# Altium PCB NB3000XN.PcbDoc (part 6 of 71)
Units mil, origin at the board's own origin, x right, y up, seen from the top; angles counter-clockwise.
Board outline 9527.56 x 6929.77 mil, 6 copper layers (Top Layer, GND+SHIELD, MidLayer1, MidLayer2, P2 - 3V3+5V0, Bottom Layer), stack 62.375 mil thick; 832 components, 1027 nets, 4655 pads, 4981 vias.
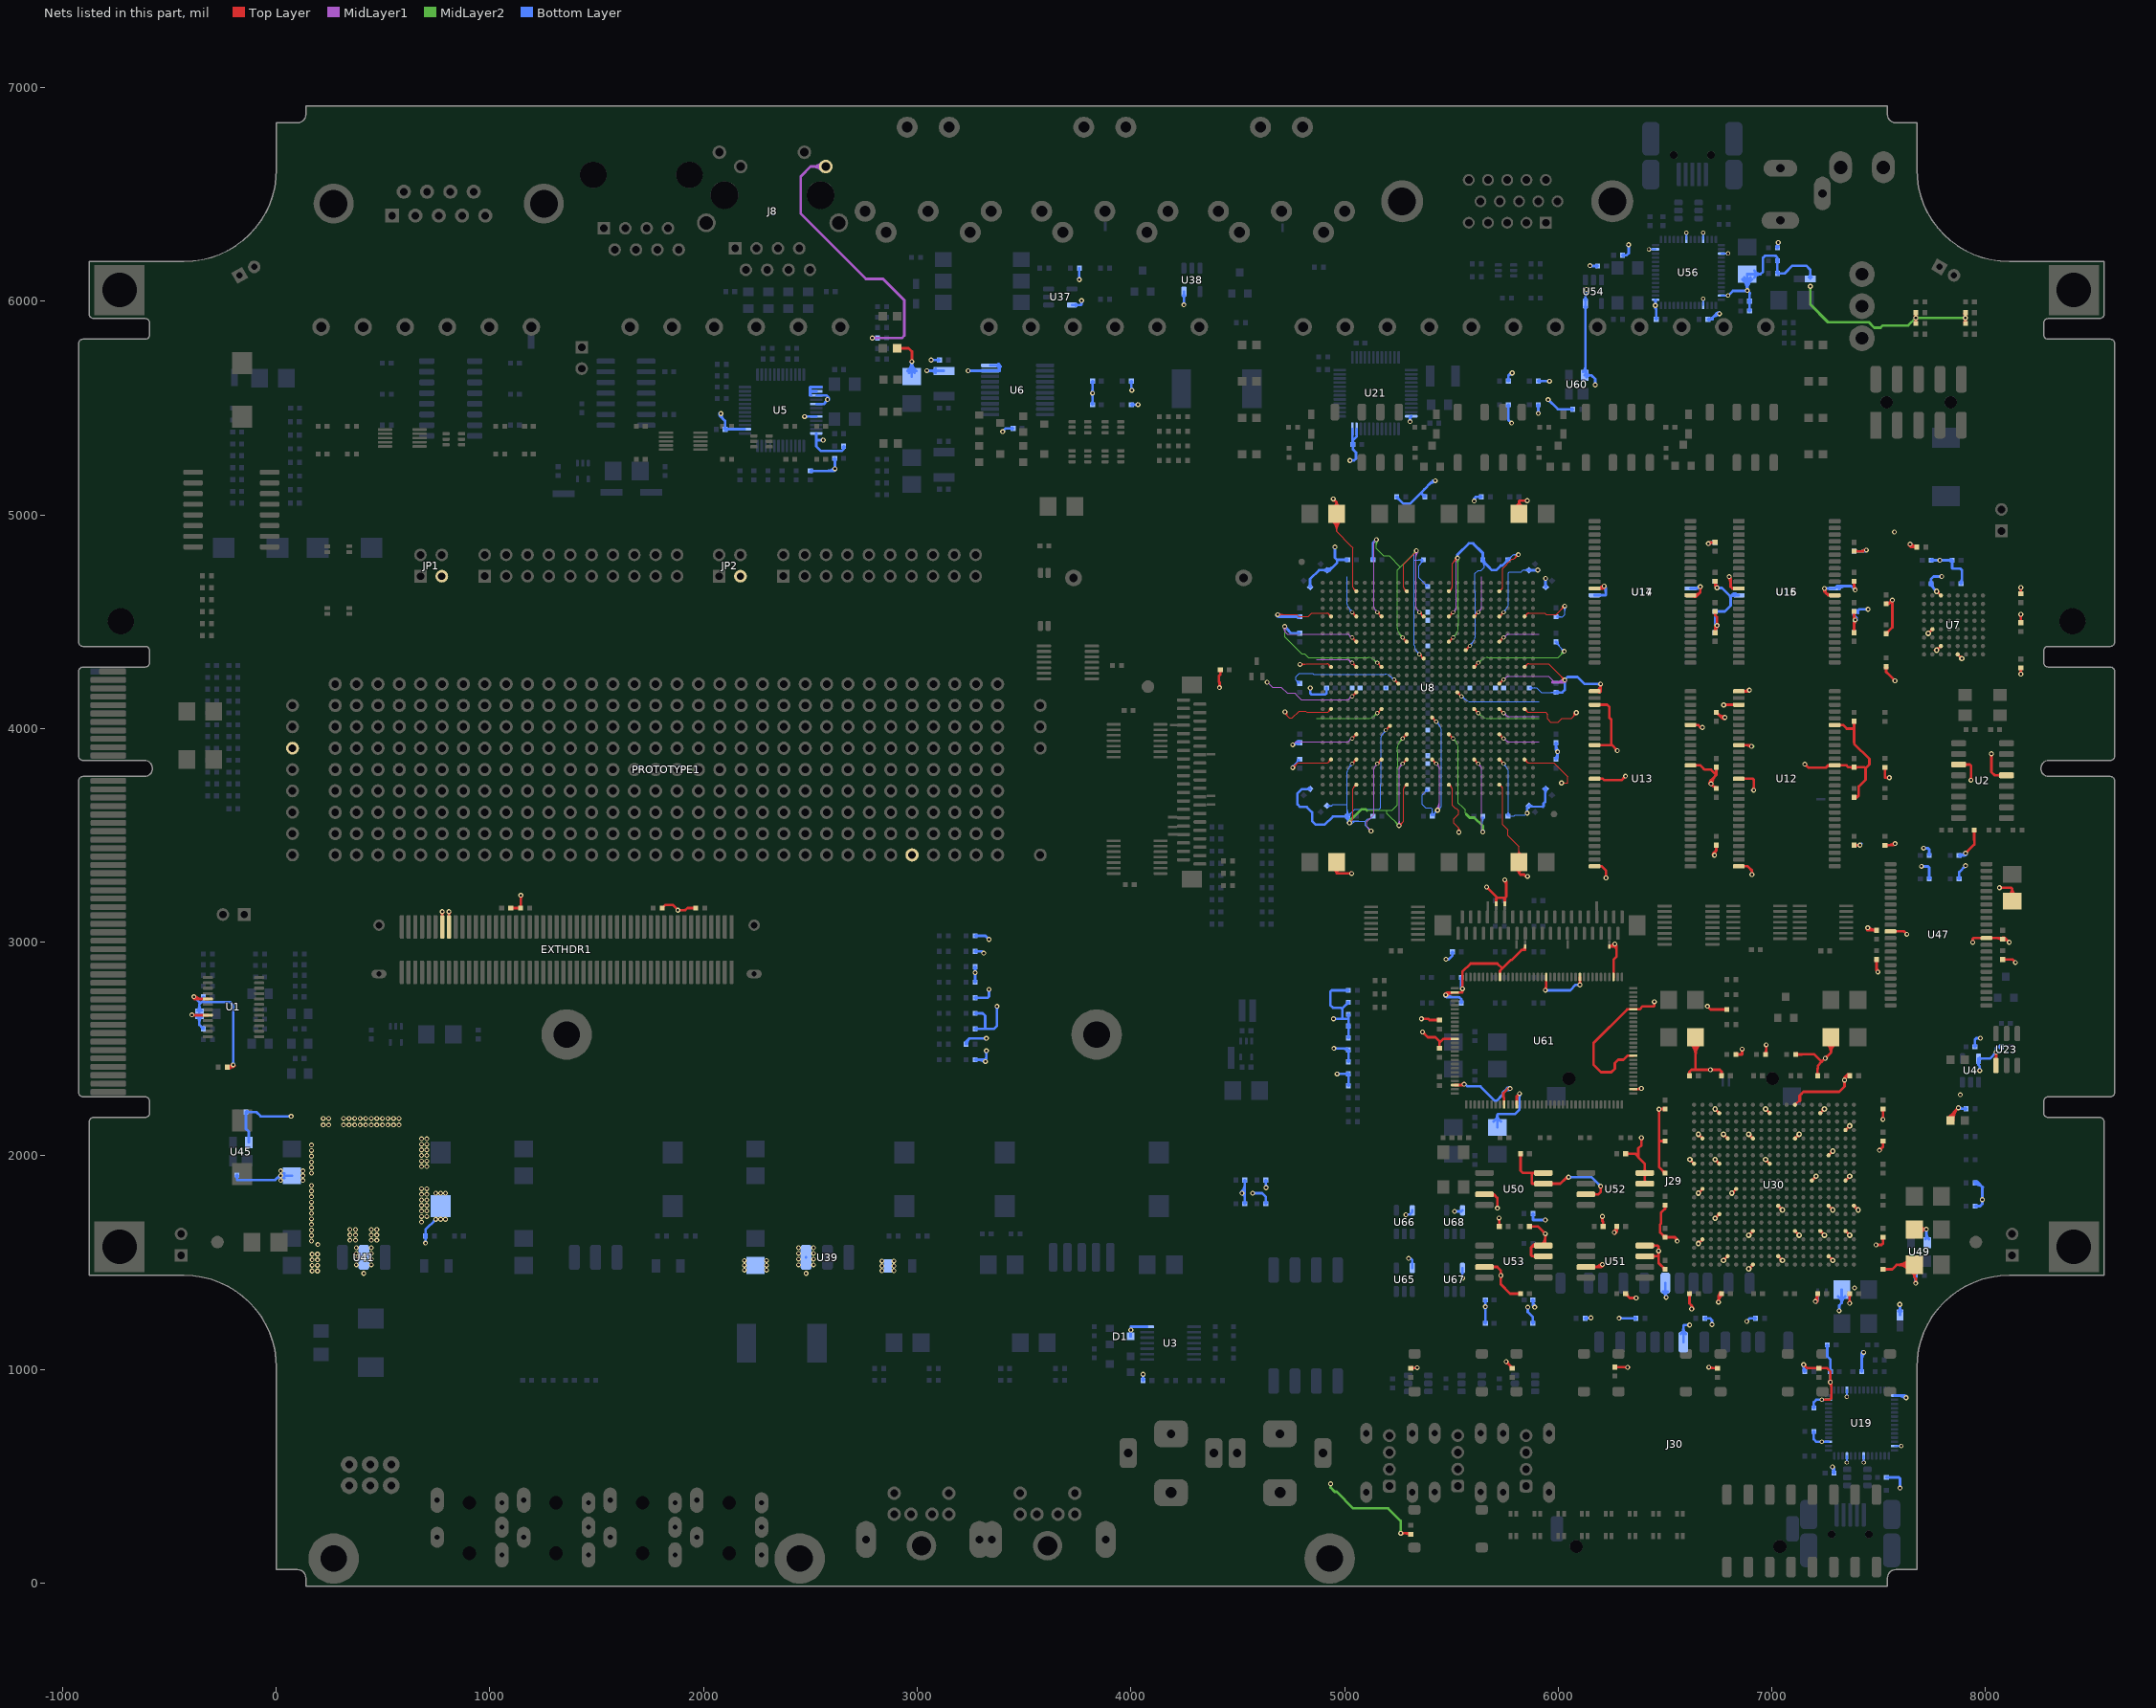
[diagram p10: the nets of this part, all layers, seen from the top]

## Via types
v1: diameter 23, hole 11.81, Top Layer to Bottom Layer, 3672 vias
v2: diameter 26, hole 11.81, Top Layer to Bottom Layer, 461 vias
v3: diameter 19, hole 11.81, Top Layer to Bottom Layer, tented both sides, 396 vias
v4: diameter 23.62, hole 11.81, Top Layer to Bottom Layer, 288 vias
v5: diameter 20, hole 11.81, Top Layer to Bottom Layer, 91 vias
v6: diameter 23, hole 11.81, Top Layer to Bottom Layer, tented both sides, 50 vias
v7: diameter 31, hole 11.81, Top Layer to Bottom Layer, 15 vias
v8: diameter 27.56, hole 11.81, Top Layer to Bottom Layer, tented both sides, 4 vias
v9: diameter 29, hole 11.81, Top Layer to Bottom Layer, 3 vias
v10: diameter 21, hole 11.81, Top Layer to Bottom Layer, 1 vias

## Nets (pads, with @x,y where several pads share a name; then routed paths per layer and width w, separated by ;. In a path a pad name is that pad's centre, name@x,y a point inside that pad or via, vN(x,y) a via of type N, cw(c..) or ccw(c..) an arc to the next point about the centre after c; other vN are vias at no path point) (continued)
3V3: C20.1 C21.1 C35.1 C36.1 C37.2 C39.2 C49.1 C50.2 C51.2 C52.2 C54.2 C55.1 C56.1 C57.1 C58.1 C59.1 C60.1 C63.1 C64.1 C65.1 C66.1 C67.1 C68.1 C69.1 C70.1 C71.1 C72.1 C73.1 C74.1 C75.1 C76.1 C77.1 C78.1 C79.1 C80.1 C81.1 C82.1 C83.1 C84.1 C85.1 C86.1 C90.2 C91.2 C92.2 C93.1 C94.1 C95.1 C96.1 C126.1 C127.1 C136.1 C137.1 C153.1 C154.1 C155.1 C156.1 C158.1 C159.2 C160.1 C161.2 C162.1 C163.2 C164.1 C165.2 C168.1 C172.2 C173.2 C174.2 C175.1 C176.1 C177.1 C185.1 C200.1 C201.1 C202.1 C203.1 C215.1 C216.1 C217.1 C218.1 C219.1 C220.1 C221.1 C222.1 C223.1 C224.1 C225.1 C226.1 C227.1 C228.1 C229.1 C231.1 C232.1 C233.1 C234.1 C235.1 C236.1 C237.1 C238.1 C239.1 C240.1 C241.1 C242.1 C243.1 C244.1 C245.1 C246.1 C247.1 C248.1 C249.1 C250.1 C251.1 C252.1 C253.1 C254.1 C255.1 C256.1 C257.1 C258.1 C259.1 C276.1 C277.1 C278.1 C279.1 C291.1 C292.1 C293.1 C294.1 C295.1 C296.1 C297.1 C298.1 C299.1 C300.1 C301.1 C302.1 C303.1 C304.1 C305.1 C307.1 C308.1 C309.1 C310.1 C311.1 C312.1 C313.1 C314.1 C315.1 C316.1 C317.1 C318.1 C319.1 C320.1 C321.1 C322.1 C323.1 C324.1 C325.1 C326.1 C327.1 C328.1 C329.1 C330.1 C331.1 C332.1 C333.1 C334.1 C335.1 D1.3 EXTHDR1.85 EXTHDR1.87 J8.12 J29.4 J30.4 JP1.3 JP2.3 L2.1 LED2.1 LED3.1 NT6.2 NT10.1 NT34.2 NT35.2 NT36.2 NT37.2 NT45.1 PROTOTYPE1.28 R21.1 R39.1 R50.2 R57.2 R59.2 R70.2 R73.2 R76.2 R77.2 R98.2 R99.2 R102.1 R103.1 R104.2 R105.1 R106.2 R107.1 R113.1 R114.1 R115.2 R131.2 R147.1 R154.2 R156.2 R158.2 R159.2 R161.1 R162.1 R195.2 R205.2 R215.1 R216.2 R217.2 R218.2 R219.2 R224.2 R225.2 R226.2 R227.2 R232.2 R234.2 R235.2 R236.2 R237.2 R238.2 R239.2 R240.2 R241.2 R242.2 R243.2 R248.2 R250.1 R251.1 R252.2 R253.1 R254.1 R255.1 R256.1 R260.2 R264.2 R265.2 R266.2 R271.2 R272.2 R273.2 R277.1 R278.2 R279.1 R280.1 R281.1 R282.1 R283.1 TP4.1 U1.5 U1.8 U2.3 U2.13 U3.14 U4.5 U5.14 U5.37 U5.38 U5.39 U5.41 U5.44 U5.48 U6.19 U6.20 U7.D8 U7.F1 U7.F7 U7.G5 U8.AB2 U8.AB5 U8.AB8 U8.AB11 U8.AB14 U8.AB19 U8.AB22 U8.AB25 U8.AE5 U8.AE11 U8.AE16 U8.AE22 U8.B5 U8.B11 U8.B16 U8.B22 U8.E2 U8.E5 U8.E8 U8.E13 U8.E16 U8.E19 U8.E22 U8.E25 U8.H5 U8.H11 U8.H16 U8.H22 U8.J18 U8.K13 U8.L2 U8.L5 U8.L8 U8.L19 U8.L25 U8.N10 U8.N22 U8.P5 U8.P17 U8.T2 U8.T8 U8.T19 U8.T22 U8.T25 U8.U14 U8.V9 U8.W5 U8.W11 U8.W16 U8.W22 U12.1 U12.3 U12.9 U12.14 U12.27 U12.43 U12.49 U13.1 U13.3 U13.9 U13.14 U13.27 U13.43 U13.49 U14.11 U14.33 U15.11 U15.33 U16.11 U16.33 U17.11 U17.33 U19.7 U19.11 U19.17 U19.27 U19.32 U19.43 U19.55 U21.12 U21.23 U21.24 U23.4 U30.A13 U30.B4 U30.B10 U30.B16 U30.D7 U30.D13 U30.D19 U30.E2 U30.E16 U30.F10 U30.H1 U30.H5 U30.H16 U30.K13 U30.K19 U30.L2 U30.L8 U30.N5 U30.N16 U30.N20 U30.R11 U30.T5 U30.T19 U30.U2 U30.U8 U30.U14 U30.W5 U30.W11 U30.W17 U30.Y8 U37.5 U38.5 U39.3 U41.2 U45.4 U47.11 U47.33 U49.4 U50.3 U50.7 U50.8 U51.3 U51.7 U51.8 U52.3 U52.7 U52.8 U53.3 U53.7 U53.8 U54.5 U56.7 U56.11 U56.17 U56.27 U56.32 U56.43 U56.55 U60.4 U61.10 U61.13 U61.40 U61.48 U61.59 U61.67 U61.75 U61.83 U61.94 U61.104 U61.115 U61.126 U65.5 U66.5 U67.5 U68.5 | length 76783.8
  Top Layer w4: R147.1@4415.19,4271.37 R147.1@4418.82,4275 ; v1(4686.86,4533.37) 4757,4533.37 4776.66,4533.37 4784.33,4525.71 4802.13,4525.71 4824,4525.71 4831.86,4525.71 4842.52,4536.37 4842.52,4536.49 4846.19,4540.15 4855.26,4540.15 4860,4540.15 4870,4540.15 4917.53,4540.15 ; v1@4690.75,4529.49 cw(c4700.14,4520.1) 4700.14,4533.37 cw(c4700.14,4546.65) v1@4690.75,4537.26 ; v1@4693.57,4526.66 cw(c4709.79,4510.44) 4709.79,4533.37 cw(c4709.79,4556.31) v1@4693.57,4540.09 ; v4(4721.3,4078.1) 4725,4074.4 4725,4065 4740.79,4049.21 4755.77,4049.21 4788.77,4082.21 4817.42,4082.21 4823.56,4076.07 4860,4076.07 4870,4076.07 4917.53,4076.07 ccw(c4917.53,4086.22) 4924.71,4079.04 ; v4@4723.03,4077.58 ccw(c4736.72,4073.49) 4726.62,4063.38 ; v4@4726.86,4076.44 ccw(c4744.01,4071.3) 4731.35,4058.65 ; v4@4730.7,4075.29 ccw(c4751.3,4069.12) 4736.09,4053.91 ; v1(4757.52,3816.71) 4780.66,3839.85 4860,3839.85 4870,3839.85 4917.53,3839.85 ; v1@4757.52,3822.21 ccw(c4757.52,3835.49) 4766.91,3826.1 ccw(c4776.3,3816.71) v1@4763.02,3816.71 ; v1@4757.52,3826.21 ccw(c4757.52,3849.14) 4773.74,3832.93 ccw(c4789.96,3816.71) v1@4767.02,3816.71 ; v1@4795.41,4296.15 cw(c4804.8,4286.76) 4804.8,4300.04 cw(c4804.8,4313.32) 4795.41,4303.93 v1(4791.52,4300.04) 4816.11,4300.04 4820,4303.93 4860,4303.93 4870,4303.93 4917.53,4303.93 cw(c4917.53,4293.78) 4924.71,4300.96 ; v1@4798.24,4293.32 cw(c4814.46,4277.11) 4814.46,4300.04 cw(c4814.46,4322.98) v1@4798.24,4306.76 ; U8.T2@4929.9,4091.57 cw(c4912.17,4091.57) 4924.71,4079.04 ; U8.L2@4929.9,4288.43 ccw(c4912.17,4288.43) 4924.71,4300.96 ; U8.T2@4937.24,4084.23 ccw(c4937.24,4066.51) 4924.71,4079.04 ; U8.L2@4937.24,4295.77 cw(c4937.24,4313.49) 4924.71,4300.96 ; C276.1@4939.62,4971.9 cw(c4900.61,4923.22) 4962.99,4923.22 ; C276.1@4942.12,4975.02 cw(c4907.29,4931.56) 4962.99,4931.56 cw(c5018.7,4931.56) C276.1@4983.86,4975.02 ; C276.1@4944.63,4978.14 cw(c4913.97,4939.89) 4962.99,4939.89 cw(c5012.02,4939.89) C276.1@4981.36,4978.14 ; C276.1@4947.13,4981.27 cw(c4920.64,4948.22) 4962.99,4948.22 cw(c5005.34,4948.22) C276.1@4978.86,4981.27 ; C276.1@4949.63,4984.39 cw(c4927.32,4956.55) 4962.99,4956.55 cw(c4998.66,4956.55) C276.1@4976.36,4984.39 ; C276.1@4962.99,4982.01 4962.99,4923.22 ; C276.1@4986.36,4971.9 ccw(c5025.37,4923.22) 4962.99,4923.22 ; v1(5023.52,3558.37) 5039.85,3574.7 5039.85,3655.26 5039.85,3660 5039.85,3670 5039.85,3717.53 ; v3(5035.67,3835.67) U8.AB5@5055.35,3855.35 ; v3(5035.67,3953.78) U8.W5@5055.35,3973.46 ; v3(5035.67,4150.63) U8.P5@5055.35,4170.31 ; v3(5035.67,4308.11) U8.L5@5055.35,4288.43 ; v3(5035.67,4426.22) U8.H5@5055.35,4406.54 ; v3(5035.67,4544.33) U8.E5@5055.35,4524.65 ; U8.AB5@5047.85,3855.35 cw(c5029.75,3855.35) 5042.55,3842.55 cw(c5055.35,3829.75) U8.AB5@5055.35,3847.85 ; U8.W5@5047.85,3973.46 cw(c5029.75,3973.46) 5042.55,3960.66 cw(c5055.35,3947.86) U8.W5@5055.35,3965.96 ; U8.P5@5047.85,4170.31 cw(c5029.75,4170.31) 5042.55,4157.51 cw(c5055.35,4144.71) U8.P5@5055.35,4162.81 ; U8.L5@5047.85,4288.43 ccw(c5029.75,4288.43) 5042.55,4301.23 ccw(c5055.35,4314.03) U8.L5@5055.35,4295.93 ; U8.H5@5047.85,4406.54 ccw(c5029.75,4406.54) 5042.55,4419.34 ccw(c5055.35,4432.14) U8.H5@5055.35,4414.04 ; U8.E5@5047.85,4524.65 ccw(c5029.75,4524.65) 5042.55,4537.45 ccw(c5055.35,4550.25) U8.E5@5055.35,4532.15 ; U8.AB5@5048.01,3855.35 cw(c5030.29,3855.35) 5042.82,3842.82 cw(c5055.35,3830.29) U8.AB5@5055.35,3848.01 ; U8.W5@5048.01,3973.46 cw(c5030.29,3973.46) 5042.82,3960.93 cw(c5055.35,3948.4) U8.W5@5055.35,3966.12 ; U8.P5@5048.01,4170.31 cw(c5030.29,4170.31) 5042.82,4157.78 cw(c5055.35,4145.25) U8.P5@5055.35,4162.97 ; U8.L5@5048.01,4288.43 ccw(c5030.29,4288.43) 5042.82,4300.96 ccw(c5055.35,4313.49) U8.L5@5055.35,4295.77 ; U8.H5@5048.01,4406.54 ccw(c5030.29,4406.54) 5042.82,4419.07 ccw(c5055.35,4431.6) U8.H5@5055.35,4413.88 ; U8.E5@5048.01,4524.65 ccw(c5030.29,4524.65) 5042.82,4537.18 ccw(c5055.35,4549.71) U8.E5@5055.35,4531.99 ; v3(5153.78,3835.67) U8.AB8@5173.46,3855.35 ; v3(5153.78,4071.89) U8.T8@5173.46,4091.57 ; v3(5153.78,4308.11) U8.L8@5173.46,4288.43 ; v3(5153.78,4544.33) U8.E8@5173.46,4524.65 ; U8.AB8@5165.96,3855.35 cw(c5147.86,3855.35) 5160.66,3842.55 cw(c5173.46,3829.75) U8.AB8@5173.46,3847.85 ; U8.T8@5165.96,4091.57 cw(c5147.86,4091.57) 5160.66,4078.77 cw(c5173.46,4065.97) U8.T8@5173.46,4084.07 ; U8.L8@5165.96,4288.43 ccw(c5147.86,4288.43) 5160.66,4301.23 ccw(c5173.46,4314.03) U8.L8@5173.46,4295.93 ; U8.E8@5165.96,4524.65 ccw(c5147.86,4524.65) 5160.66,4537.45 ccw(c5173.46,4550.25) U8.E8@5173.46,4532.15 ; U8.AB8@5166.12,3855.35 cw(c5148.4,3855.35) 5160.93,3842.82 cw(c5173.46,3830.29) U8.AB8@5173.46,3848.01 ; U8.T8@5166.12,4091.57 cw(c5148.4,4091.57) 5160.93,4079.04 cw(c5173.46,4066.51) U8.T8@5173.46,4084.23 ; U8.L8@5166.12,4288.43 ccw(c5148.4,4288.43) 5160.93,4300.96 ccw(c5173.46,4313.49) U8.L8@5173.46,4295.77 ; U8.E8@5166.12,4524.65 ccw(c5148.4,4524.65) 5160.93,4537.18 ccw(c5173.46,4549.71) U8.E8@5173.46,4531.99 ; v3(5193.15,3993.15) U8.V9@5212.83,4012.83 ; U8.V9@5205.33,4012.83 cw(c5187.23,4012.83) 5200.03,4000.03 cw(c5212.83,3987.23) U8.V9@5212.83,4005.33 ; U8.V9@5205.49,4012.83 cw(c5187.77,4012.83) 5200.3,4000.3 cw(c5212.83,3987.77) U8.V9@5212.83,4005.49 ; v3(5232.52,4229.37) U8.N10@5252.2,4209.69 ; U8.N10@5244.7,4209.69 ccw(c5226.6,4209.69) 5239.4,4222.49 ccw(c5252.2,4235.29) U8.N10@5252.2,4217.19 ; U8.N10@5244.86,4209.69 ccw(c5227.14,4209.69) 5239.67,4222.22 ccw(c5252.2,4234.75) U8.N10@5252.2,4217.03 ; v1(5255.52,3545.37) 5276.07,3565.92 5276.07,3660 ; v1@5255.52,3550.87 ccw(c5255.52,3564.15) 5264.91,3554.76 ccw(c5274.3,3545.37) v1@5261.02,3545.37 ; v1@5255.52,3554.87 ccw(c5255.52,3577.81) 5271.74,3561.59 ccw(c5287.96,3545.37) v1@5265.02,3545.37 ; v3(5271.89,3835.67) U8.AB11@5291.57,3855.35 ; v3(5271.89,3953.78) U8.W11@5291.57,3973.46 ; v3(5271.89,4426.22) U8.H11@5291.57,4406.54 ; 5276.07,3658.37 5276.07,3655.26 5276.07,3660 ; U8.AB11@5284.07,3855.35 cw(c5265.97,3855.35) 5278.77,3842.55 cw(c5291.57,3829.75) U8.AB11@5291.57,3847.85 ; U8.W11@5284.07,3973.46 cw(c5265.97,3973.46) 5278.77,3960.66 cw(c5291.57,3947.86) U8.W11@5291.57,3965.96 ; U8.H11@5284.07,4406.54 ccw(c5265.97,4406.54) 5278.77,4419.34 ccw(c5291.57,4432.14) U8.H11@5291.57,4414.04 ; U8.AE11@5284.23,3737.24 cw(c5266.51,3737.24) 5279.04,3724.71 ; U8.AB11@5284.23,3855.35 cw(c5266.51,3855.35) 5279.04,3842.82 cw(c5291.57,3830.29) U8.AB11@5291.57,3848.01 ; U8.W11@5284.23,3973.46 cw(c5266.51,3973.46) 5279.04,3960.93 cw(c5291.57,3948.4) U8.W11@5291.57,3966.12 ; U8.H11@5284.23,4406.54 ccw(c5266.51,4406.54) 5279.04,4419.07 ccw(c5291.57,4431.6) U8.H11@5291.57,4413.88 ; U8.B11@5284.23,4642.76 ccw(c5266.51,4642.76) 5279.04,4655.29 ; U8.AE11@5291.57,3729.9 ccw(c5291.57,3712.17) 5279.04,3724.71 ; U8.B11@5291.57,4650.1 cw(c5291.57,4667.83) 5279.04,4655.29 ; 5306.86,4800.65 5276.07,4769.86 5276.07,4724.74 5276.07,4720 5276.07,4710 5276.07,4662.47 ccw(c5286.22,4662.47) 5279.04,4655.29 ; 5306.86,4800.71 5339.52,4833.37 5337.54,4833.37 v1(5336.67,4832.5) ; v3(5350.63,4347.48) U8.K13@5370.31,4327.8 ; v3(5350.63,4544.33) U8.E13@5370.31,4524.65 ; U8.K13@5362.81,4327.8 ccw(c5344.71,4327.8) 5357.51,4340.6 ccw(c5370.31,4353.4) U8.K13@5370.31,4335.3 ; U8.E13@5362.81,4524.65 ccw(c5344.71,4524.65) 5357.51,4537.45 ccw(c5370.31,4550.25) U8.E13@5370.31,4532.15 ; U8.K13@5362.97,4327.8 ccw(c5345.25,4327.8) 5357.78,4340.33 ccw(c5370.31,4352.86) U8.K13@5370.31,4335.14 ; U8.E13@5362.97,4524.65 ccw(c5345.25,4524.65) 5357.78,4537.18 ccw(c5370.31,4549.71) U8.E13@5370.31,4531.99 ; U8.AB14@5409.69,3847.85 cw(c5409.69,3829.75) 5422.49,3842.55 cw(c5435.29,3855.35) U8.AB14@5417.19,3855.35 ; U8.AB14@5409.69,3848.01 cw(c5409.69,3830.29) 5422.22,3842.82 cw(c5434.75,3855.35) U8.AB14@5417.03,3855.35 ; U8.AB14@5409.69,3855.35 v3(5429.37,3835.67) ; U8.U14@5409.69,4044.7 cw(c5409.69,4026.6) 5422.49,4039.4 cw(c5435.29,4052.2) U8.U14@5417.19,4052.2 ; U8.U14@5409.69,4044.86 cw(c5409.69,4027.14) 5422.22,4039.67 cw(c5434.75,4052.2) U8.U14@5417.03,4052.2 ; U8.U14@5409.69,4052.2 v3(5429.37,4032.52) ; U8.AE16@5488.43,3729.9 cw(c5488.43,3712.17) 5500.96,3724.71 ; U8.W16@5488.43,3965.96 cw(c5488.43,3947.86) 5501.23,3960.66 cw(c5514.03,3973.46) U8.W16@5495.93,3973.46 ; U8.W16@5488.43,3966.12 cw(c5488.43,3948.4) 5500.96,3960.93 cw(c5513.49,3973.46) U8.W16@5495.77,3973.46 ; U8.W16@5488.43,3973.46 v3(5508.11,3953.78) ; U8.H16@5488.43,4406.54 v3(5508.11,4426.22) ; U8.H16@5488.43,4413.88 ccw(c5488.43,4431.6) 5500.96,4419.07 ccw(c5513.49,4406.54) U8.H16@5495.77,4406.54 ; U8.H16@5488.43,4414.04 ccw(c5488.43,4432.14) 5501.23,4419.34 ccw(c5514.03,4406.54) U8.H16@5495.93,4406.54 ; U8.E16@5488.43,4524.65 v3(5508.11,4544.33) ; U8.E16@5488.43,4531.99 ccw(c5488.43,4549.71) 5500.96,4537.18 ccw(c5513.49,4524.65) U8.E16@5495.77,4524.65 ; U8.E16@5488.43,4532.15 ccw(c5488.43,4550.25) 5501.23,4537.45 ccw(c5514.03,4524.65) U8.E16@5495.93,4524.65 ; U8.B16@5488.43,4650.1 ccw(c5488.43,4667.83) 5500.96,4655.29 ; U8.AE16@5495.77,3737.24 ccw(c5513.49,3737.24) 5500.96,3724.71 ; U8.B16@5495.77,4642.76 cw(c5513.49,4642.76) 5500.96,4655.29 ; v1@5519.36,4798.37 cw(c5496.42,4798.37) 5512.64,4782.16 cw(c5528.86,4765.94) v1@5528.86,4788.87 ; v1@5523.36,4798.37 cw(c5510.08,4798.37) 5519.47,4788.99 cw(c5528.86,4779.6) v1@5528.86,4792.87 ; U8.P17@5527.8,4162.81 cw(c5527.8,4144.71) 5540.6,4157.51 cw(c5553.4,4170.31) U8.P17@5535.3,4170.31 ; U8.P17@5527.8,4162.97 cw(c5527.8,4145.25) 5540.33,4157.78 cw(c5552.86,4170.31) U8.P17@5535.14,4170.31 ; U8.P17@5527.8,4170.31 v3(5547.48,4150.63) ; v1(5528.86,4798.37) 5503.93,4773.45 5503.93,4724.74 5503.93,4720 5503.93,4710 5503.93,4662.47 cw(c5493.78,4662.47) 5500.96,4655.29 ; v4@5529,3522.76 ccw(c5519.52,3535) 5535,3535 ccw(c5550.48,3535) v4@5541,3522.76 ; v4@5531.44,3519.6 ccw(c5525.83,3526.85) 5535,3526.85 ccw(c5544.17,3526.85) v4@5538.56,3519.6 ; v4(5535,3515) 5535,3535 5512.5,3557.5 5512.5,3576.7 5535.17,3599.37 5535.17,3614.58 5522.25,3627.5 5517.5,3627.5 5503.93,3641.07 5503.93,3660 5503.93,3670 5503.93,3717.53 ccw(c5493.78,3717.53) 5500.96,3724.71 ; U8.J18@5567.17,4367.17 v3(5586.85,4386.85) ; U8.J18@5567.17,4374.51 ccw(c5567.17,4392.23) 5579.7,4379.7 ccw(c5592.23,4367.17) U8.J18@5574.51,4367.17 ; U8.J18@5567.17,4374.67 ccw(c5567.17,4392.77) 5579.97,4379.97 ccw(c5592.77,4367.17) U8.J18@5574.67,4367.17 ; U8.AB19@5606.54,3847.85 cw(c5606.54,3829.75) 5619.34,3842.55 cw(c5632.14,3855.35) U8.AB19@5614.04,3855.35 ; U8.AB19@5606.54,3848.01 cw(c5606.54,3830.29) 5619.07,3842.82 cw(c5631.6,3855.35) U8.AB19@5613.88,3855.35 ; U8.AB19@5606.54,3855.35 v3(5626.22,3835.67) ; U8.T19@5606.54,4084.07 cw(c5606.54,4065.97) 5619.34,4078.77 cw(c5632.14,4091.57) U8.T19@5614.04,4091.57 ; U8.T19@5606.54,4084.23 cw(c5606.54,4066.51) 5619.07,4079.04 cw(c5631.6,4091.57) U8.T19@5613.88,4091.57 ; U8.T19@5606.54,4091.57 v3(5626.22,4071.89) ; U8.L19@5606.54,4288.43 v3(5626.22,4308.11) ; U8.L19@5606.54,4295.77 ccw(c5606.54,4313.49) 5619.07,4300.96 ccw(c5631.6,4288.43) U8.L19@5613.88,4288.43 ; U8.L19@5606.54,4295.93 ccw(c5606.54,4314.03) 5619.34,4301.23 ccw(c5632.14,4288.43) U8.L19@5614.04,4288.43 ; U8.E19@5606.54,4524.65 v3(5626.22,4544.33) ; U8.E19@5606.54,4531.99 ccw(c5606.54,4549.71) 5619.07,4537.18 ccw(c5631.6,4524.65) U8.E19@5613.88,4524.65 ; U8.E19@5606.54,4532.15 ccw(c5606.54,4550.25) 5619.34,4537.45 ccw(c5632.14,4524.65) U8.E19@5614.04,4524.65 ; U8.AB22@5724.65,3847.85 cw(c5724.65,3829.75) 5737.45,3842.55 cw(c5750.25,3855.35) U8.AB22@5732.15,3855.35 ; U8.AB22@5724.65,3848.01 cw(c5724.65,3830.29) 5737.18,3842.82 cw(c5749.71,3855.35) U8.AB22@5731.99,3855.35 ; U8.AB22@5724.65,3855.35 v3(5744.33,3835.67) ; U8.W22@5724.65,3965.96 cw(c5724.65,3947.86) 5737.45,3960.66 cw(c5750.25,3973.46) U8.W22@5732.15,3973.46 ; U8.W22@5724.65,3966.12 cw(c5724.65,3948.4) 5737.18,3960.93 cw(c5749.71,3973.46) U8.W22@5731.99,3973.46 ; U8.W22@5724.65,3973.46 v3(5744.33,3953.78) ; U8.T22@5724.65,4084.07 cw(c5724.65,4065.97) 5737.45,4078.77 cw(c5750.25,4091.57) U8.T22@5732.15,4091.57 ; U8.T22@5724.65,4084.23 cw(c5724.65,4066.51) 5737.18,4079.04 cw(c5749.71,4091.57) U8.T22@5731.99,4091.57 ; U8.T22@5724.65,4091.57 v3(5744.33,4071.89) ; U8.N22@5724.65,4209.69 v3(5744.33,4229.37) ; U8.N22@5724.65,4217.03 ccw(c5724.65,4234.75) 5737.18,4222.22 ccw(c5749.71,4209.69) U8.N22@5731.99,4209.69 ; U8.N22@5724.65,4217.19 ccw(c5724.65,4235.29) 5737.45,4222.49 ccw(c5750.25,4209.69) U8.N22@5732.15,4209.69 ; U8.H22@5724.65,4406.54 v3(5744.33,4426.22) ; U8.H22@5724.65,4413.88 ccw(c5724.65,4431.6) 5737.18,4419.07 ccw(c5749.71,4406.54) U8.H22@5731.99,4406.54 ; U8.H22@5724.65,4414.04 ccw(c5724.65,4432.14) 5737.45,4419.34 ccw(c5750.25,4406.54) U8.H22@5732.15,4406.54 ; U8.E22@5724.65,4524.65 v3(5744.33,4544.33) ; U8.E22@5724.65,4531.99 ccw(c5724.65,4549.71) 5737.18,4537.18 ccw(c5749.71,4524.65) U8.E22@5731.99,4524.65 ; U8.E22@5724.65,4532.15 ccw(c5724.65,4550.25) 5737.45,4537.45 ccw(c5750.25,4524.65) U8.E22@5732.15,4524.65 ; 5748.52,3541.71 5749.11,3541.12 ; v1@5804.02,4814.37 cw(c5781.09,4814.37) 5797.31,4798.16 cw(c5813.52,4781.94) v1@5813.52,4804.87 ; v1@5808.02,4814.37 cw(c5794.75,4814.37) 5804.14,4804.99 cw(c5813.52,4795.6) v1@5813.52,4808.87 ; C279.1@5809.31,3415.5 ccw(c5807.31,3425) 5817.01,3425 ccw(c5826.71,3425) C279.1@5824.71,3415.5 ; C279.1@5810.13,3411.59 ccw(c5808.34,3420.07) 5817.01,3420.07 ccw(c5825.67,3420.07) C279.1@5823.89,3411.59 ; v1(5813.52,4814.37) 5792.16,4793.01 5783.76,4793.01 5740.15,4749.4 5740.15,4737.37 5740.15,4735 5740.15,4724.74 5740.15,4720 5740.15,4710 5740.15,4662.47 ; C279.1@5817.01,3375 5817.01,3447.22 5765.19,3499.04 5765.19,3525.04 5749.11,3541.12 ; U8.T25@5842.76,4084.23 cw(c5842.76,4066.51) 5855.29,4079.04 ; U8.L25@5842.76,4295.77 ccw(c5842.76,4313.49) 5855.29,4300.96 ; v1@5848.52,3308.37 v1(5856.86,3308.37) ; U8.T25@5850.1,4091.57 ccw(c5867.83,4091.57) 5855.29,4079.04 ; U8.L25@5850.1,4288.43 cw(c5867.83,4288.43) 5855.29,4300.96 ; v4(6015,3745) 6015.87,3745.87 6045.19,3745.87 6045.19,3774.1 5979.44,3839.85 5920,3839.85 5910,3839.85 5862.47,3839.85 ; v1@6021.02,4227.71 ccw(c5998.09,4227.71) 6014.31,4243.93 ccw(c6030.52,4260.14) v1@6030.52,4237.21 ; v1@6021.02,4573.71 cw(c5998.09,4573.71) 6014.31,4557.49 cw(c6030.52,4541.27) v1@6030.52,4564.21 ; v1@6025.02,4227.71 ccw(c6011.75,4227.71) 6021.14,4237.1 ccw(c6030.52,4246.49) v1@6030.52,4233.21 ; v1@6025.02,4573.71 cw(c6011.75,4573.71) 6021.13,4564.32 cw(c6030.52,4554.93) v1@6030.52,4568.21 ; v1(6030.52,4227.71) 5958.19,4300.04 5954.3,4303.93 5931.86,4303.93 5920,4303.93 5910,4303.93 5862.47,4303.93 ccw(c5862.47,4293.78) 5855.29,4300.96 ; v1(6030.52,4573.71) 5990.19,4533.37 5945,4533.37 5938.22,4540.15 5923.52,4540.15 ; 6065,4050 ccw(c6040.4,4074.6) v4@6075.19,4074.91 ; 6071.74,4056.74 ccw(c6053.77,4074.72) v4@6079.19,4074.95 ; 6076.79,4061.79 cw(c6085,4053.57) v4@6085,4065.19 ; 6078.49,4063.49 ccw(c6067.13,4074.84) v4@6083.19,4074.98 ; v4(6085,4075) 6085,4070 6062.5,4047.5 6017,4047.5 5999.5,4030 5965,4030 5950.36,4044.64 5950.36,4066.53 5940.82,4076.07 5920,4076.07 5910,4076.07 5862.47,4076.07 cw(c5862.47,4086.22) 5855.29,4079.04 ; 4917.53,3839.85 ccw(c4917.53,3850) 4924.71,3842.82 ; 4917.53,3839.85 ccw(c4917.53,3850) 4924.71,3842.82 ; 4917.53,4540.15 cw(c4917.53,4530) 4924.71,4537.18 ; 4917.53,4540.15 cw(c4917.53,4530) 4924.71,4537.18 ; 4924.71,3842.82 ccw(c4912.17,3855.35) 4929.9,3855.35 cw(c4912.17,3855.35) 4924.71,3842.82 ; 4924.71,3842.82 cw(c4937.24,3830.29) 4937.24,3848.01 ccw(c4937.24,3830.29) 4924.71,3842.82 ; 4924.71,4537.18 cw(c4912.17,4524.65) 4929.9,4524.65 ccw(c4912.17,4524.65) 4924.71,4537.18 ; 4924.71,4537.18 ccw(c4937.24,4549.71) 4937.24,4531.99 cw(c4937.24,4549.71) 4924.71,4537.18 ; 4962.99,4923.22 5026.84,4859.37 5028.96,4857.25 ; 5028.96,4857.25 5031.25,4854.96 5039.85,4846.37 ; 5028.96,4857.25 5039.85,4846.37 ; 5039.85,3717.53 cw(c5050,3717.53) 5042.82,3724.71 ; 5039.85,3717.53 cw(c5050,3717.53) 5042.82,3724.71 ; 5039.85,4662.47 ccw(c5050,4662.47) 5042.82,4655.29 ; 5039.85,4662.47 ccw(c5050,4662.47) 5042.82,4655.29 ; 5039.85,4662.47 5039.85,4710 5039.85,4720 5039.85,4724.74 5039.85,4768 5039.85,4775.15 5039.85,4846.37 ; 5042.82,3724.71 cw(c5055.35,3712.17) 5055.35,3729.9 ccw(c5055.35,3712.17) 5042.82,3724.71 ; 5042.82,3724.71 ccw(c5030.29,3737.24) 5048.01,3737.24 cw(c5030.29,3737.24) 5042.82,3724.71 ; 5042.82,4655.29 ccw(c5055.35,4667.83) 5055.35,4650.1 cw(c5055.35,4667.83) 5042.82,4655.29 ; 5042.82,4655.29 cw(c5030.29,4642.76) 5048.01,4642.76 ccw(c5030.29,4642.76) 5042.82,4655.29 ; 5048.47,3848.47 cw(c5035.67,3861.28) 5035.67,3843.17 ccw(c5035.67,3861.28) 5048.47,3848.47 ; 5048.47,3848.47 ccw(c5061.28,3835.67) 5043.17,3835.67 cw(c5061.28,3835.67) 5048.47,3848.47 ; 5048.47,3966.58 cw(c5035.67,3979.39) 5035.67,3961.28 ccw(c5035.67,3979.39) 5048.47,3966.58 ; 5048.47,3966.58 ccw(c5061.28,3953.78) 5043.17,3953.78 cw(c5061.28,3953.78) 5048.47,3966.58 ; 5048.47,4163.43 cw(c5035.67,4176.24) 5035.67,4158.13 ccw(c5035.67,4176.24) 5048.47,4163.43 ; 5048.47,4163.43 ccw(c5061.28,4150.63) 5043.17,4150.63 cw(c5061.28,4150.63) 5048.47,4163.43 ; 5048.47,4295.31 ccw(c5035.67,4282.5) 5035.67,4300.61 cw(c5035.67,4282.5) 5048.47,4295.31 ; 5048.47,4295.31 cw(c5061.28,4308.11) 5043.17,4308.11 ccw(c5061.28,4308.11) 5048.47,4295.31 ; 5048.47,4413.42 ccw(c5035.67,4400.61) 5035.67,4418.72 cw(c5035.67,4400.61) 5048.47,4413.42 ; 5048.47,4413.42 cw(c5061.28,4426.22) 5043.17,4426.22 ccw(c5061.28,4426.22) 5048.47,4413.42 ; 5048.47,4531.53 ccw(c5035.67,4518.72) 5035.67,4536.83 cw(c5035.67,4518.72) 5048.47,4531.53 ; 5048.47,4531.53 cw(c5061.28,4544.33) 5043.17,4544.33 ccw(c5061.28,4544.33) 5048.47,4531.53 ; 5166.58,3848.47 cw(c5153.78,3861.28) 5153.78,3843.17 ccw(c5153.78,3861.28) 5166.58,3848.47 ; 5166.58,3848.47 ccw(c5179.39,3835.67) 5161.28,3835.67 cw(c5179.39,3835.67) 5166.58,3848.47 ; 5166.58,4084.69 cw(c5153.78,4097.5) 5153.78,4079.39 ccw(c5153.78,4097.5) 5166.58,4084.69 ; 5166.58,4084.69 ccw(c5179.39,4071.89) 5161.28,4071.89 cw(c5179.39,4071.89) 5166.58,4084.69 ; 5166.58,4295.31 cw(c5179.39,4308.11) 5161.28,4308.11 ccw(c5179.39,4308.11) 5166.58,4295.31 ; 5166.58,4295.31 ccw(c5153.78,4282.5) 5153.78,4300.61 cw(c5153.78,4282.5) 5166.58,4295.31 ; 5166.58,4531.53 cw(c5179.39,4544.33) 5161.28,4544.33 ccw(c5179.39,4544.33) 5166.58,4531.53 ; 5166.58,4531.53 ccw(c5153.78,4518.72) 5153.78,4536.83 cw(c5153.78,4518.72) 5166.58,4531.53 ; 5205.95,4005.95 cw(c5193.15,4018.76) 5193.15,4000.65 ccw(c5193.15,4018.76) 5205.95,4005.95 ; 5205.95,4005.95 ccw(c5218.76,3993.15) 5200.65,3993.15 cw(c5218.76,3993.15) 5205.95,4005.95 ; 5245.32,4216.57 cw(c5258.13,4229.37) 5240.02,4229.37 ccw(c5258.13,4229.37) 5245.32,4216.57 ; 5245.32,4216.57 ccw(c5232.52,4203.76) 5232.52,4221.87 cw(c5232.52,4203.76) 5245.32,4216.57 ; 5276.07,3660 5276.07,3670 5276.07,3717.53 cw(c5286.22,3717.53) 5279.04,3724.71 ; 5284.69,3848.47 cw(c5271.89,3861.28) 5271.89,3843.17 ccw(c5271.89,3861.28) 5284.69,3848.47 ; 5284.69,3848.47 ccw(c5297.5,3835.67) 5279.39,3835.67 cw(c5297.5,3835.67) 5284.69,3848.47 ; 5284.69,3966.58 ccw(c5297.5,3953.78) 5279.39,3953.78 cw(c5297.5,3953.78) 5284.69,3966.58 ; 5284.69,3966.58 cw(c5271.89,3979.39) 5271.89,3961.28 ccw(c5271.89,3979.39) 5284.69,3966.58 ; 5284.69,4413.42 cw(c5297.5,4426.22) 5279.39,4426.22 ccw(c5297.5,4426.22) 5284.69,4413.42 ; 5284.69,4413.42 ccw(c5271.89,4400.61) 5271.89,4418.72 cw(c5271.89,4400.61) 5284.69,4413.42 ; 5363.43,4334.68 cw(c5376.24,4347.48) 5358.13,4347.48 ccw(c5376.24,4347.48) 5363.43,4334.68 ; 5363.43,4334.68 ccw(c5350.63,4321.87) 5350.63,4339.98 cw(c5350.63,4321.87) 5363.43,4334.68 ; 5363.43,4531.53 cw(c5376.24,4544.33) 5358.13,4544.33 ccw(c5376.24,4544.33) 5363.43,4531.53 ; 5363.43,4531.53 ccw(c5350.63,4518.72) 5350.63,4536.83 cw(c5350.63,4518.72) 5363.43,4531.53 ; 5416.57,3848.47 cw(c5403.76,3835.67) 5421.87,3835.67 ccw(c5403.76,3835.67) 5416.57,3848.47 ; 5416.57,3848.47 ccw(c5429.37,3861.28) 5429.37,3843.17 cw(c5429.37,3861.28) 5416.57,3848.47 ; 5416.57,4045.32 cw(c5403.76,4032.52) 5421.87,4032.52 ccw(c5403.76,4032.52) 5416.57,4045.32 ; 5416.57,4045.32 ccw(c5429.37,4058.13) 5429.37,4040.02 cw(c5429.37,4058.13) 5416.57,4045.32 ; 5495.31,3966.58 cw(c5482.5,3953.78) 5500.61,3953.78 ccw(c5482.5,3953.78) 5495.31,3966.58 ; 5495.31,3966.58 ccw(c5508.11,3979.39) 5508.11,3961.28 cw(c5508.11,3979.39) 5495.31,3966.58 ; 5495.31,4413.42 cw(c5508.11,4400.61) 5508.11,4418.72 ccw(c5508.11,4400.61) 5495.31,4413.42 ; 5495.31,4413.42 ccw(c5482.5,4426.22) 5500.61,4426.22 cw(c5482.5,4426.22) 5495.31,4413.42 ; 5495.31,4531.53 cw(c5508.11,4518.72) 5508.11,4536.83 ccw(c5508.11,4518.72) 5495.31,4531.53 ; 5495.31,4531.53 ccw(c5482.5,4544.33) 5500.61,4544.33 cw(c5482.5,4544.33) 5495.31,4531.53 ; 5534.68,4163.43 cw(c5521.87,4150.63) 5539.98,4150.63 ccw(c5521.87,4150.63) 5534.68,4163.43 ; 5534.68,4163.43 ccw(c5547.48,4176.24) 5547.48,4158.13 cw(c5547.48,4176.24) 5534.68,4163.43 ; 5574.05,4374.05 cw(c5586.85,4361.24) 5586.85,4379.35 ccw(c5586.85,4361.24) 5574.05,4374.05 ; 5574.05,4374.05 ccw(c5561.24,4386.85) 5579.35,4386.85 cw(c5561.24,4386.85) 5574.05,4374.05 ; 5613.42,3848.47 cw(c5600.61,3835.67) 5618.72,3835.67 ccw(c5600.61,3835.67) 5613.42,3848.47 ; 5613.42,3848.47 ccw(c5626.22,3861.28) 5626.22,3843.17 cw(c5626.22,3861.28) 5613.42,3848.47 ; 5613.42,4084.69 cw(c5600.61,4071.89) 5618.72,4071.89 ccw(c5600.61,4071.89) 5613.42,4084.69 ; 5613.42,4084.69 ccw(c5626.22,4097.5) 5626.22,4079.39 cw(c5626.22,4097.5) 5613.42,4084.69 ; 5613.42,4295.31 cw(c5626.22,4282.5) 5626.22,4300.61 ccw(c5626.22,4282.5) 5613.42,4295.31 ; 5613.42,4295.31 ccw(c5600.61,4308.11) 5618.72,4308.11 cw(c5600.61,4308.11) 5613.42,4295.31 ; 5613.42,4531.53 cw(c5626.22,4518.72) 5626.22,4536.83 ccw(c5626.22,4518.72) 5613.42,4531.53 ; 5613.42,4531.53 ccw(c5600.61,4544.33) 5618.72,4544.33 cw(c5600.61,4544.33) 5613.42,4531.53 ; 5731.53,3848.47 cw(c5718.72,3835.67) 5736.83,3835.67 ccw(c5718.72,3835.67) 5731.53,3848.47 ; 5731.53,3848.47 ccw(c5744.33,3861.28) 5744.33,3843.17 cw(c5744.33,3861.28) 5731.53,3848.47 ; 5731.53,3966.58 cw(c5718.72,3953.78) 5736.83,3953.78 ccw(c5718.72,3953.78) 5731.53,3966.58 ; 5731.53,3966.58 ccw(c5744.33,3979.39) 5744.33,3961.28 cw(c5744.33,3979.39) 5731.53,3966.58 ; 5731.53,4084.69 cw(c5718.72,4071.89) 5736.83,4071.89 ccw(c5718.72,4071.89) 5731.53,4084.69 ; 5731.53,4084.69 ccw(c5744.33,4097.5) 5744.33,4079.39 cw(c5744.33,4097.5) 5731.53,4084.69 ; 5731.53,4216.57 cw(c5744.33,4203.76) 5744.33,4221.87 ccw(c5744.33,4203.76) 5731.53,4216.57 ; 5731.53,4216.57 ccw(c5718.72,4229.37) 5736.83,4229.37 cw(c5718.72,4229.37) 5731.53,4216.57 ; 5731.53,4413.42 cw(c5744.33,4400.61) 5744.33,4418.72 ccw(c5744.33,4400.61) 5731.53,4413.42 ; 5731.53,4413.42 ccw(c5718.72,4426.22) 5736.83,4426.22 cw(c5718.72,4426.22) 5731.53,4413.42 ; 5731.53,4531.53 cw(c5744.33,4518.72) 5744.33,4536.83 ccw(c5744.33,4518.72) 5731.53,4531.53 ; 5731.53,4531.53 ccw(c5718.72,4544.33) 5736.83,4544.33 cw(c5718.72,4544.33) 5731.53,4531.53 ; 5737.18,3724.71 cw(c5730,3717.53) 5740.15,3717.53 ; 5737.18,3724.71 cw(c5730,3717.53) 5740.15,3717.53 ; 5737.18,3724.71 ccw(c5724.65,3712.17) 5724.65,3729.9 cw(c5724.65,3712.17) 5737.18,3724.71 ; 5737.18,3724.71 cw(c5749.71,3737.24) 5731.99,3737.24 ccw(c5749.71,3737.24) 5737.18,3724.71 ; 5737.18,4655.29 ccw(c5730,4662.47) 5740.15,4662.47 ; 5737.18,4655.29 ccw(c5730,4662.47) 5740.15,4662.47 ; 5737.18,4655.29 cw(c5724.65,4667.83) 5724.65,4650.1 ccw(c5724.65,4667.83) 5737.18,4655.29 ; 5737.18,4655.29 ccw(c5749.71,4642.76) 5731.99,4642.76 cw(c5749.71,4642.76) 5737.18,4655.29 ; 5740.15,3717.53 5740.15,3670 5740.15,3660 5740.15,3636 5740.15,3628.41 5740.15,3550.08 5740.19,3550.04 5744.12,3546.11 5749.11,3541.12 ; 5855.29,3842.82 ccw(c5862.47,3850) 5862.47,3839.85 ; 5855.29,3842.82 ccw(c5862.47,3850) 5862.47,3839.85 ; 5855.29,3842.82 cw(c5867.83,3855.35) 5850.1,3855.35 ccw(c5867.83,3855.35) 5855.29,3842.82 ; 5855.29,3842.82 ccw(c5842.76,3830.29) 5842.76,3848.01 cw(c5842.76,3830.29) 5855.29,3842.82 ; 5855.29,4537.18 cw(c5862.47,4530) 5862.47,4540.15 ; 5855.29,4537.18 cw(c5862.47,4530) 5862.47,4540.15 ; 5855.29,4537.18 ccw(c5867.83,4524.65) 5850.1,4524.65 cw(c5867.83,4524.65) 5855.29,4537.18 ; 5855.29,4537.18 cw(c5842.76,4549.71) 5842.76,4531.99 ccw(c5842.76,4549.71) 5855.29,4537.18 ; 5862.47,4540.15 5910,4540.15 5920,4540.15 5923.52,4540.15 ; 5923.52,4540.15 5924.74,4540.15 5923.52,4540.15
  Top Layer w8: v2@6616.3,1974.11 cw(c6616.3,1952.38) 6631.66,1967.75 cw(c6647.03,1983.11) v2@6625.3,1983.11 ; v2(6616.3,1983.11) U30.Y8@6635.98,1963.43 ; U30.Y8@6630.14,1963.43 ccw(c6616.04,1963.43) 6626.01,1973.4 ccw(c6635.98,1983.37) U30.Y8@6635.98,1969.27 ; v2(6655.67,1589.41) U30.W17@6675.35,1609.09 ; v2@6655.67,1598.41 ccw(c6655.67,1620.14) 6671.03,1604.77 ccw(c6686.4,1589.41) v2@6664.67,1589.41 ; v2(6655.67,1825.63) U30.W11@6675.35,1845.31 ; v2@6655.67,1834.63 ccw(c6655.67,1856.36) 6671.03,1840.99 ccw(c6686.4,1825.63) v2@6664.67,1825.63 ; v2@6655.67,2092.22 cw(c6655.67,2070.49) 6671.03,2085.86 cw(c6686.4,2101.22) v2@6664.67,2101.22 ; v2(6655.67,2101.22) U30.W5@6675.35,2081.54 ; U30.W17@6669.51,1609.09 cw(c6655.41,1609.09) 6665.38,1599.12 cw(c6675.35,1589.15) U30.W17@6675.35,1603.25 ; U30.W11@6669.51,1845.31 cw(c6655.41,1845.31) 6665.38,1835.34 cw(c6675.35,1825.37) U30.W11@6675.35,1839.47 ; U30.W5@6669.51,2081.54 ccw(c6655.41,2081.54) 6665.38,2091.51 ccw(c6675.35,2101.48) U30.W5@6675.35,2087.38 ; v2(6734.41,1707.52) U30.U14@6754.09,1727.2 ; v2@6734.41,1716.52 ccw(c6734.41,1738.25) 6749.77,1722.88 ccw(c6765.14,1707.52) v2@6743.41,1707.52 ; v2@6734.41,1974.11 cw(c6734.41,1952.38) 6749.77,1967.75 cw(c6765.14,1983.11) v2@6743.41,1983.11 ; v2(6734.41,1983.11) U30.U8@6754.09,1963.43 ; v2@6734.41,2210.33 cw(c6734.41,2188.6) 6749.77,2203.97 cw(c6765.14,2219.33) v2@6743.41,2219.33 ; v2(6734.41,2219.33) U30.U2@6754.09,2199.65 ; U30.U14@6748.25,1727.2 cw(c6734.15,1727.2) 6744.12,1717.23 cw(c6754.09,1707.26) U30.U14@6754.09,1721.36 ; U30.U8@6748.25,1963.43 ccw(c6734.15,1963.43) 6744.12,1973.4 ccw(c6754.09,1983.37) U30.U8@6754.09,1969.27 ; U30.U2@6748.25,2199.65 ccw(c6734.15,2199.65) 6744.12,2209.62 ccw(c6754.09,2219.59) U30.U2@6754.09,2205.49 ; v2(6773.78,1510.67) U30.T19@6793.46,1530.35 ; v2@6773.78,1519.67 ccw(c6773.78,1541.4) 6789.14,1526.03 ccw(c6804.51,1510.67) v2@6782.78,1510.67 ; v2@6773.78,2092.22 cw(c6773.78,2070.49) 6789.14,2085.86 cw(c6804.51,2101.22) v2@6782.78,2101.22 ; v2(6773.78,2101.22) U30.T5@6793.46,2081.54 ; U30.T19@6787.62,1530.35 cw(c6773.52,1530.35) 6783.49,1520.38 cw(c6793.46,1510.41) U30.T19@6793.46,1524.51 ; U30.T5@6787.62,2081.54 ccw(c6773.52,2081.54) 6783.49,2091.51 ccw(c6793.46,2101.48) U30.T5@6793.46,2087.38 ; v2(6813.15,1825.63) U30.R11@6832.83,1845.31 ; v2@6813.15,1834.63 ccw(c6813.15,1856.36) 6828.51,1840.99 ccw(c6843.88,1825.63) v2@6822.15,1825.63 ; U30.R11@6826.99,1845.31 cw(c6812.89,1845.31) 6822.86,1835.34 cw(c6832.83,1825.37) U30.R11@6832.83,1839.47 ; v2(6891.89,1471.3) U30.N20@6911.57,1490.98 ; v2@6891.89,1480.3 ccw(c6891.89,1502.03) 6907.25,1486.66 ccw(c6922.62,1471.3) v2@6900.89,1471.3 ; v2(6891.89,1628.78) U30.N16@6911.57,1648.46 ; v2@6891.89,1637.78 ccw(c6891.89,1659.51) 6907.25,1644.14 ccw(c6922.62,1628.78) v2@6900.89,1628.78 ; v2@6891.89,2092.22 cw(c6891.89,2070.49) 6907.25,2085.86 cw(c6922.62,2101.22) v2@6900.89,2101.22 ; v2(6891.89,2101.22) U30.N5@6911.57,2081.54 ; U30.N20@6905.73,1490.98 cw(c6891.63,1490.98) 6901.6,1481.01 cw(c6911.57,1471.04) U30.N20@6911.57,1485.14 ; U30.N16@6905.73,1648.46 cw(c6891.63,1648.46) 6901.6,1638.49 cw(c6911.57,1628.52) U30.N16@6911.57,1642.62 ; U30.N5@6905.73,2081.54 ccw(c6891.63,2081.54) 6901.6,2091.51 ccw(c6911.57,2101.48) U30.N5@6911.57,2087.38 ; v2@6970.63,1974.11 cw(c6970.63,1952.38) 6985.99,1967.75 cw(c7001.36,1983.11) v2@6979.63,1983.11 ; v2(6970.63,1983.11) U30.L8@6990.31,1963.43 ; v2@6970.63,2210.33 cw(c6970.63,2188.6) 6985.99,2203.97 cw(c7001.36,2219.33) v2@6979.63,2219.33 ; v2(6970.63,2219.33) U30.L2@6990.31,2199.65 ; U30.L8@6984.47,1963.43 ccw(c6970.37,1963.43) 6980.34,1973.4 ccw(c6990.31,1983.37) U30.L8@6990.31,1969.27 ; U30.L2@6984.47,2199.65 ccw(c6970.37,2199.65) 6980.34,2209.62 ccw(c6990.31,2219.59) U30.L2@6990.31,2205.49 ; U30.K19@7029.69,1524.51 cw(c7029.69,1510.41) 7039.66,1520.38 cw(c7049.63,1530.35) U30.K19@7035.53,1530.35 ; U30.K19@7029.69,1530.35 v2(7049.37,1510.67) ; U30.K13@7029.69,1760.73 cw(c7029.69,1746.63) 7039.66,1756.6 cw(c7049.63,1766.57) U30.K13@7035.53,1766.57 ; U30.K13@7029.69,1766.57 v2(7049.37,1746.89) ; v2@7040.37,1510.67 ccw(c7018.64,1510.67) 7034.01,1526.03 ccw(c7049.37,1541.4) v2@7049.37,1519.67 ; v2@7040.37,1746.89 ccw(c7018.64,1746.89) 7034.01,1762.25 ccw(c7049.37,1777.62) v2@7049.37,1755.89 ; U30.H16@7108.43,1642.62 cw(c7108.43,1628.52) 7118.4,1638.49 cw(c7128.37,1648.46) U30.H16@7114.27,1648.46 ; U30.H16@7108.43,1648.46 v2(7128.11,1628.78) ; U30.H5@7108.43,2081.54 v2(7128.11,2101.22) ; U30.H5@7108.43,2087.38 ccw(c7108.43,2101.48) 7118.4,2091.51 ccw(c7128.37,2081.54) U30.H5@7114.27,2081.54 ; U30.H1@7108.43,2239.02 7128.11,2258.7 ; U30.H1@7108.43,2244.86 ccw(c7108.43,2258.96) 7118.4,2248.99 ccw(c7128.37,2239.02) U30.H1@7114.27,2239.02 ; v2@7119.11,1628.78 ccw(c7097.38,1628.78) 7112.75,1644.14 ccw(c7128.11,1659.51) v2@7128.11,1637.78 ; v2@7119.11,2101.22 cw(c7097.38,2101.22) 7112.75,2085.86 cw(c7128.11,2070.49) v2@7128.11,2092.22 ; U30.F10@7187.17,1884.68 v2(7206.85,1904.37) ; U30.F10@7187.17,1890.53 ccw(c7187.17,1904.63) 7197.14,1894.66 ccw(c7207.11,1884.68) U30.F10@7193.01,1884.68 ; v2@7197.85,1904.37 cw(c7176.12,1904.37) 7191.49,1889.01 cw(c7206.85,1873.64) v2@7206.85,1895.37 ; U30.E16@7226.54,1642.62 cw(c7226.54,1628.52) 7236.51,1638.49 cw(c7246.48,1648.46) U30.E16@7232.38,1648.46 ; U30.E16@7226.54,1648.46 v2(7246.22,1628.78) ; U30.E2@7226.54,2199.65 v2(7246.22,2219.33) ; U30.E2@7226.54,2205.49 ccw(c7226.54,2219.59) 7236.51,2209.62 ccw(c7246.48,2199.65) U30.E2@7232.38,2199.65 ; v2@7237.22,1628.78 ccw(c7215.49,1628.78) 7230.86,1644.14 ccw(c7246.22,1659.51) v2@7246.22,1637.78 ; v2@7237.22,2219.33 cw(c7215.49,2219.33) 7230.86,2203.97 cw(c7246.22,2188.6) v2@7246.22,2210.33 ; U30.D19@7265.91,1524.51 cw(c7265.91,1510.41) 7275.88,1520.38 cw(c7285.85,1530.35) U30.D19@7271.75,1530.35 ; U30.D19@7265.91,1530.35 v2(7285.59,1510.67) ; U30.D13@7265.91,1760.73 cw(c7265.91,1746.63) 7275.88,1756.6 cw(c7285.85,1766.57) U30.D13@7271.75,1766.57 ; U30.D13@7265.91,1766.57 v2(7285.59,1746.89) ; U30.D7@7265.91,2002.8 v2(7285.59,2022.48) ; U30.D7@7265.91,2008.64 ccw(c7265.91,2022.74) 7275.88,2012.77 ccw(c7285.85,2002.8) U30.D7@7271.75,2002.8 ; v2@7276.59,1510.67 ccw(c7254.86,1510.67) 7270.23,1526.03 ccw(c7285.59,1541.4) v2@7285.59,1519.67 ; v2@7276.59,1746.89 ccw(c7254.86,1746.89) 7270.23,1762.25 ccw(c7285.59,1777.62) v2@7285.59,1755.89 ; v2@7276.59,2022.48 cw(c7254.86,2022.48) 7270.23,2007.12 cw(c7285.59,1991.75) v2@7285.59,2013.48 ; U30.B16@7344.65,1642.62 cw(c7344.65,1628.52) 7354.62,1638.49 cw(c7364.59,1648.46) U30.B16@7350.49,1648.46 ; U30.B16@7344.65,1648.46 v2(7364.33,1628.78) ; U30.B10@7344.65,1884.68 v2(7364.33,1904.37) ; U30.B10@7344.65,1890.53 ccw(c7344.65,1904.63) 7354.62,1894.66 ccw(c7364.59,1884.68) U30.B10@7350.49,1884.68 ; U30.B4@7344.65,2120.91 v2(7364.33,2140.59) ; U30.B4@7344.65,2126.75 ccw(c7344.65,2140.85) 7354.62,2130.88 ccw(c7364.59,2120.91) U30.B4@7350.49,2120.91 ; v2@7355.33,1628.78 ccw(c7333.6,1628.78) 7348.97,1644.14 ccw(c7364.33,1659.51) v2@7364.33,1637.78 ; v2@7355.33,1904.37 cw(c7333.6,1904.37) 7348.97,1889.01 cw(c7364.33,1873.64) v2@7364.33,1895.37 ; v2@7355.33,2140.59 cw(c7333.6,2140.59) 7348.97,2125.23 cw(c7364.33,2109.86) v2@7364.33,2131.59 ; U30.A13@7384.02,1760.73 cw(c7384.02,1746.63) 7393.99,1756.6 cw(c7403.96,1766.57) U30.A13@7389.86,1766.57 ; U30.A13@7384.02,1766.57 v2(7403.7,1746.89) ; v2@7394.7,1746.89 ccw(c7372.97,1746.89) 7388.34,1762.25 ccw(c7403.7,1777.62) v2@7403.7,1755.89 ; v2(7731.89,4445.63) U7.G5@7751.58,4465.32 ; v2@7731.89,4454.63 ccw(c7731.89,4476.36) 7747.25,4460.99 ccw(c7762.62,4445.63) v2@7740.89,4445.63 ; U7.G5@7745.58,4465.32 cw(c7731.09,4465.32) 7741.33,4455.07 cw(c7751.58,4444.83) U7.G5@7751.58,4459.32 ; v2(7771.26,4366.89) U7.F7@7790.95,4386.57 ; v2@7771.26,4375.89 ccw(c7771.26,4397.62) 7786.62,4382.25 ccw(c7801.99,4366.89) v2@7780.26,4366.89 ; v2@7771.26,4633.48 cw(c7771.26,4611.75) 7786.62,4627.12 cw(c7801.99,4642.48) v2@7780.26,4642.48 ; v2(7771.26,4642.48) U7.F1@7790.95,4622.8 ; U7.F7@7784.95,4386.57 cw(c7770.46,4386.57) 7780.7,4376.33 cw(c7790.95,4366.09) U7.F7@7790.95,4380.57 ; U7.F1@7784.95,4622.8 ccw(c7770.46,4622.8) 7780.7,4633.04 ccw(c7790.95,4643.28) U7.F1@7790.95,4628.8 ; U7.D8@7869.69,4341.2 cw(c7869.69,4326.72) 7879.93,4336.96 cw(c7890.17,4347.2) U7.D8@7875.69,4347.2 ; U7.D8@7869.69,4347.2 v2(7889.37,4327.52) ; v2@7880.37,4327.52 ccw(c7858.64,4327.52) 7874.01,4342.88 ccw(c7889.37,4358.25) v2@7889.37,4336.52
